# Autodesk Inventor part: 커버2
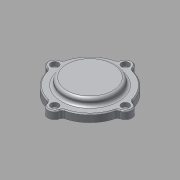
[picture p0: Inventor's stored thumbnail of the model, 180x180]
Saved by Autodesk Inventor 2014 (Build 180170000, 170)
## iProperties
Company: 한국ATC센터
Created: 2015-12
Part Number: 커버2
Document SubType Name: Modeling
Designer: mdu
Density: 2.71 g/cm^3
Material: 알루미늄 6061
Appearance: Aluminum - Flat
Author: mdu
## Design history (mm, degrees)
sketch "스케치1"
  geometry: C1 r 1.621 at (0, 6.75) reference; C2 r 1.621 at (-37, -30.25) reference; C3 r 1.621 at (0, -67.25) reference; C4 r 1.621 at (37, -30.25) reference; C5 r 10 at (0, -30.25) reference; C6 r 12 at (0, -30.25); C7 r 24.5 at (0, -30.25) reference; A1 r 3 centre (-38.77, -20.408) between (-38.239, -23.361) and (-35.862, -21.146) reference; A2 r 7 centre (-37, -30.25) between (-38.239, -23.361) and (-38.239, -37.139) reference; A3 r 3 centre (-38.77, -40.092) between (-35.862, -39.354) and (-38.239, -37.139) reference; A4 r 37 centre (0, -30.25) between (-35.862, -39.354) and (-9.104, -66.113) reference; A5 r 3 centre (-9.842, -69.02) between (-6.889, -68.489) and (-9.104, -66.113) reference; A6 r 7 centre (0, -67.25) between (-6.889, -68.489) and (6.889, -68.489) reference; A7 r 3 centre (9.842, -69.02) between (9.104, -66.112) and (6.889, -68.489) reference; A8 r 37 centre (0, -30.25) between (9.104, -66.112) and (35.863, -39.354) reference; A9 r 3 centre (38.77, -40.092) between (38.239, -37.139) and (35.863, -39.354) reference; A10 r 7 centre (37, -30.25) between (38.239, -37.139) and (38.239, -23.361) reference; A11 r 3 centre (38.77, -20.408) between (35.863, -21.146) and (38.239, -23.361) reference; A12 r 37 centre (0, -30.25) between (35.863, -21.146) and (9.104, 5.612) reference; A13 r 3 centre (9.842, 8.52) between (6.889, 7.989) and (9.104, 5.612) reference; A14 r 7 centre (0, 6.75) between (6.889, 7.989) and (-6.889, 7.989) reference; A15 r 3 centre (-9.842, 8.52) between (-9.104, 5.612) and (-6.889, 7.989) reference; A16 r 37 centre (0, -30.25) between (-9.104, 5.612) and (-35.862, -21.146) reference; 1 further point
  constraints: 1 centre point, 1 coincident
  dimensions: "d2" = 2 radial gap between concentric circles of C6 C5
extrude "돌출1" new body sketch "스케치1" distance "d0" = 8; taper "d1" = 0 deg
sketch "스케치2"
  geometry: C1 r 23.5 at (0, -30.25) reference; C2 r 12 at (0, -30.25) reference; 1 further point
extrude "돌출2" join sketch "스케치2" distance "d4" = 5; taper "d5" = 0 deg
sketch "스케치3"
  geometry: C1 r 23.5 at (0, 0) reference; C2 r 20.5 at (0, 0); 1 further point
  constraints: 1 centre point
  dimensions: "d6" = 3 radial gap between concentric circles of C2 C1
node "작업 평면1"
extrude "돌출3" join sketch "스케치3" stored distance "d7" = 5; taper "d8" = 0 deg
fillet "모깎기1" dims "d9" = 3
sketch "스케치4"
  geometry: C1 r 12 at (0, -30.25) reference; C2 r 27 at (0, -30.25); 1 further point
  constraints: 1 centre point
  dimensions: "d10" = 15 radial gap between concentric circles of C1 C2
extrude "돌출4" join sketch "스케치4" distance "d11" = 7; taper "d12" = 0 deg
fillet "모깎기2" dims "d13" = 3
chamfer "모따기1" distance "d14" = 1; stored, may be unused: second distance "d15" = 2, angle "d16" = 45 deg
node "작업점1"
  node "작업축1"
chamfer "모따기2" distance "d24" = 1; stored, may be unused: second distance "d25" = 2, angle "d26" = 45 deg
hole "구멍6" diameter "d43" = 4.5; stored, may be unused: countersink angle "d47" = 90 deg, drill point angle "d49" = 118 deg; dims "d41" = 10, "d42" = 10, "d44" = 6, "d45" = 8, "d46" = 4.4, "d48" = 8
fillet "모깎기4" dims "d60" = 3
node "솔리드1"
pattern_circular "원형 패턴1" dims angle "d51" = 360 deg
node "참조1"
node "참조2"
